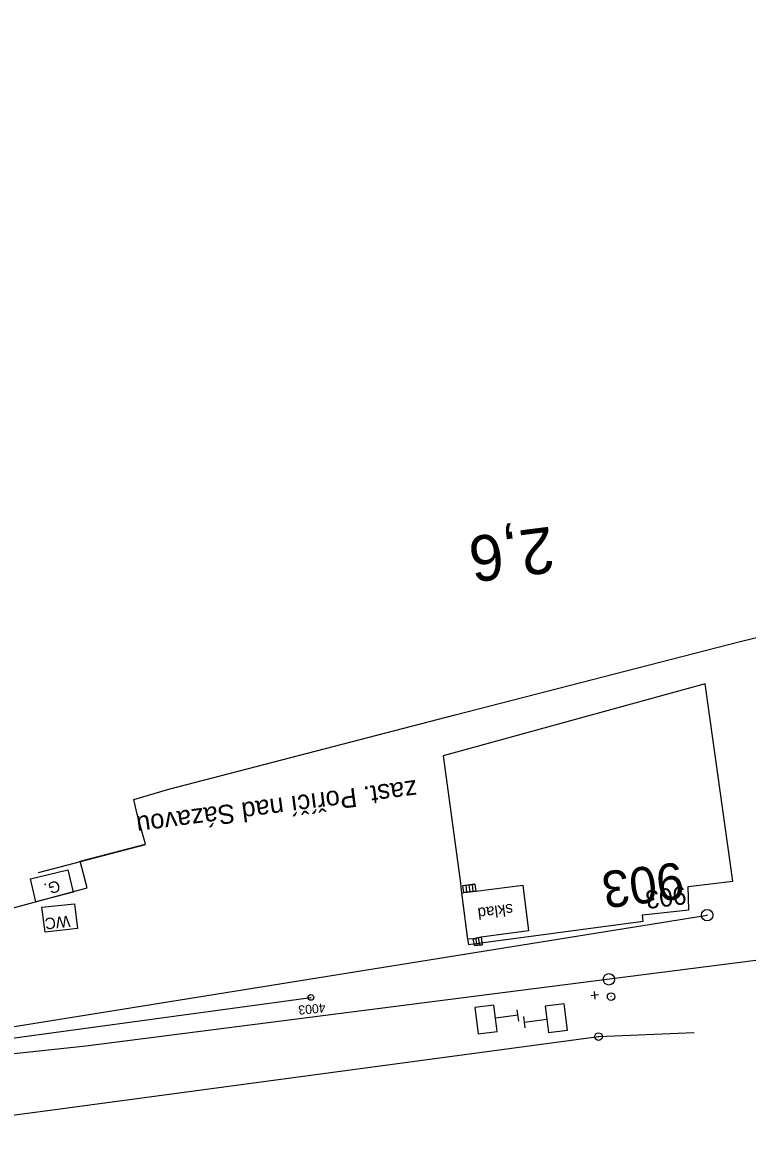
# Model space of a CAD drawing. Extents: x -728800 to -728100, y -1073200 to -1072700.
# Drawn here: x -728437.4 to -728342.2, y -1073054.1 to -1072906.2 of the extents above; entities that cross this region are included whole.
import ezdxf

# ---------------------------------------------------------------- set-up
doc = ezdxf.new("R2010")
doc.units = 0
for name, color, linetype in [('A1_OBVOD Spravy železnic', 7, 'Continuous'), ('B4_Bodové pole', 7, 'Continuous'), ('B6_JŽM', 7, 'Continuous')]:
    doc.layers.add(name, color=color, linetype=linetype)

msp = doc.modelspace()

# ---------------------------------------------------------------- linework, layer by layer
at = {"layer": 'A1_OBVOD Spravy železnic'}
for points in [[(-728503.24, -1073052.34), (-728501.95, -1073043.29), (-728501.19, -1073037.94), (-728499.78, -1073032.61), (-728497.54, -1073030.15), (-728493.68, -1073027.94), (-728443.97, -1073014.59), (-728443.68, -1073014.51), (-728441.09, -1073023.23), (-728428.92, -1073019.94), (-728429.82, -1073016.43), (-728427.49, -1073015.84), (-728421.24, -1073014.23), (-728422.34, -1073010.27), (-728422.77, -1073008.34), (-728418.21, -1073007), (-728380.57, -1072997.2), (-728343.1, -1072987.57), (-728330.49, -1072984.52), (-728326.79, -1072988.95)], [(-728347.72, -1072993.16), (-728382.13, -1073002.62), (-728379.86, -1073019.33), (-728379.76, -1073020.32), (-728379.15, -1073025.03)], [(-728379.15, -1073025.03), (-728378.98, -1073026.45), (-728378.8, -1073027.41), (-728355.85, -1073024.35), (-728355.97, -1073023.5), (-728349.85, -1073022.84), (-728349.94, -1073019.8), (-728344.1, -1073019.09), (-728347.72, -1072993.16)], [(-728503.24, -1073052.34), (-728496.81, -1073052.21), (-728491.97, -1073053.44), (-728477.97, -1073053.19), (-728470.97, -1073054.08), (-728434.43, -1073049.27), (-728361.73, -1073039.5), (-728349.17, -1073038.98)]]:
    msp.add_lwpolyline(points, dxfattribs=at)
at = {"layer": 'B4_Bodové pole'}
for p, q in [((-728347.41, -1073023.53), (-728347.51, -1073023.54)), ((-728347.41, -1073023.53), (-728347.51, -1073023.54)), ((-728502.09, -1073048.37), (-728399.52, -1073034.36)), ((-728399.54, -1073034.36), (-728399.49, -1073034.37))]:
    msp.add_line(p, q, dxfattribs=at)
msp.add_lwpolyline([(-728665.96, -1072915.44), (-728594.71, -1073015.73), (-728502.09, -1073048.37), (-728347.46, -1073023.54)], dxfattribs=at)
for centre, radius in [((-728347.46, -1073023.54), 0.756), ((-728347.46, -1073023.54), 0.756), ((-728399.52, -1073034.36), 0.378)]:
    msp.add_circle(centre, radius, dxfattribs=at)
at = {"layer": 'B6_JŽM'}
for p, q in [((-728378.35, -1073019.5), (-728378.25, -1073020.44)), ((-728379.18, -1073019.6), (-728379.08, -1073020.53)), ((-728378.76, -1073019.55), (-728378.66, -1073020.49)), ((-728377.69, -1073027.49), (-728377.84, -1073026.57)), ((-728377.34, -1073027.46), (-728377.5, -1073026.52)), ((-728361.72, -1073034.02), (-728362.71, -1073034.15)), ((-728362.15, -1073034.58), (-728362.27, -1073033.59)), ((-728360.02, -1073034.23), (-728360.12, -1073034.25)), ((-728372.21, -1073037.46), (-728372.4, -1073035.97)), ((-728371.58, -1073036.86), (-728371.39, -1073038.35)), ((-728361.78, -1073039.5), (-728361.68, -1073039.5))]:
    msp.add_line(p, q, dxfattribs=at)
for points in [[(-728300.81, -1073024.35), (-728320.8, -1073026.91), (-728374.01, -1073033.72), (-728429.1, -1073040.75), (-728461.93, -1073044.27), (-728481.2, -1073044.81), (-728499.35, -1073043.65), (-728506.01, -1073042.74), (-728514.57, -1073041.33), (-728535.85, -1073036), (-728561.35, -1073026.11), (-728583.96, -1073013.52), (-728603.76, -1072998.89), (-728619.19, -1072984.42), (-728634.19, -1072966.82), (-728646.08, -1072949.19), (-728656.18, -1072930.07), (-728664.99, -1072910.23), (-728668.63, -1072901.81), (-728681.25, -1072876.02), (-728691.89, -1072859.66)], [(-728435.3, -1073017.95), (-728421.27, -1073014.25)], [(-728436.35, -1073018.78), (-728431.48, -1073017.61), (-728430.76, -1073020.54), (-728435.67, -1073021.78), (-728436.35, -1073018.78)], [(-728379.57, -1073019.64), (-728378.04, -1073019.45), (-728378, -1073019.46)], [(-728379.57, -1073019.64), (-728378, -1073019.46), (-728377.87, -1073020.4)], [(-728379.69, -1073020.59), (-728379.44, -1073020.57), (-728377.87, -1073020.4), (-728371.69, -1073019.62), (-728370.92, -1073025.62), (-728377.14, -1073026.45), (-728378.22, -1073026.64), (-728378.91, -1073026.7), (-728379.69, -1073020.59)], [(-728377.87, -1073020.4), (-728379.44, -1073020.57), (-728379.57, -1073019.64)], [(-728434.86, -1073022.51), (-728430.59, -1073022.04), (-728430.19, -1073025.28), (-728434.44, -1073025.77), (-728434.86, -1073022.51)], [(-728378.22, -1073026.64), (-728377.14, -1073026.45), (-728377.01, -1073027.44)], [(-728377.01, -1073027.44), (-728378.03, -1073027.52), (-728378.22, -1073026.64)], [(-728378.03, -1073027.52), (-728377.03, -1073027.45), (-728377.01, -1073027.44)], [(-728372.3, -1073036.71), (-728375.28, -1073037.09), (-728375.5, -1073035.36), (-728377.98, -1073035.68), (-728377.54, -1073039.15), (-728375.06, -1073038.83), (-728375.28, -1073037.09)], [(-728371.48, -1073037.61), (-728368.51, -1073037.23), (-728368.29, -1073038.96), (-728365.81, -1073038.65), (-728366.25, -1073035.18), (-728368.73, -1073035.49), (-728368.51, -1073037.23)]]:
    msp.add_lwpolyline(points, dxfattribs=at)
for centre, radius in [((-728360.36, -1073031.98), 0.75), ((-728360.07, -1073034.24), 0.5), ((-728361.73, -1073039.5), 0.499)]:
    msp.add_circle(centre, radius, dxfattribs=at)

# ---------------------------------------------------------------- texts
at = {"layer": 'B4_Bodové pole'}
for s, height, rotation, p in [('903', 4.8, 187.2914, (-728350.88, -1073016.54)), ('903', 2.4, 187.2914, (-728350.36, -1073019.69)), ('4003', 1.2, 185.1886, (-728397.66, -1073035.12))]:
    msp.add_text(s, height=height, rotation=rotation, dxfattribs=at).set_placement(p)
at = {"layer": 'B6_JŽM'}
for s, height, rotation, p in [('2,6', 6, 187.2914, (-728367.97, -1072972.46)), ('zast. Poříčí nad Sázavou', 2.5, 187.4528, (-728385.73, -1073005.76)), ('G.', 1.5, 194.1214, (-728432.68, -1073018.94)), ('sklad', 1.5, 187.1581, (-728373.04, -1073022.03)), ('WC', 1.5, 186.3417, (-728431.24, -1073023.58))]:
    msp.add_text(s, height=height, rotation=rotation, dxfattribs=at).set_placement(p)

doc.saveas('drawing.dxf')
